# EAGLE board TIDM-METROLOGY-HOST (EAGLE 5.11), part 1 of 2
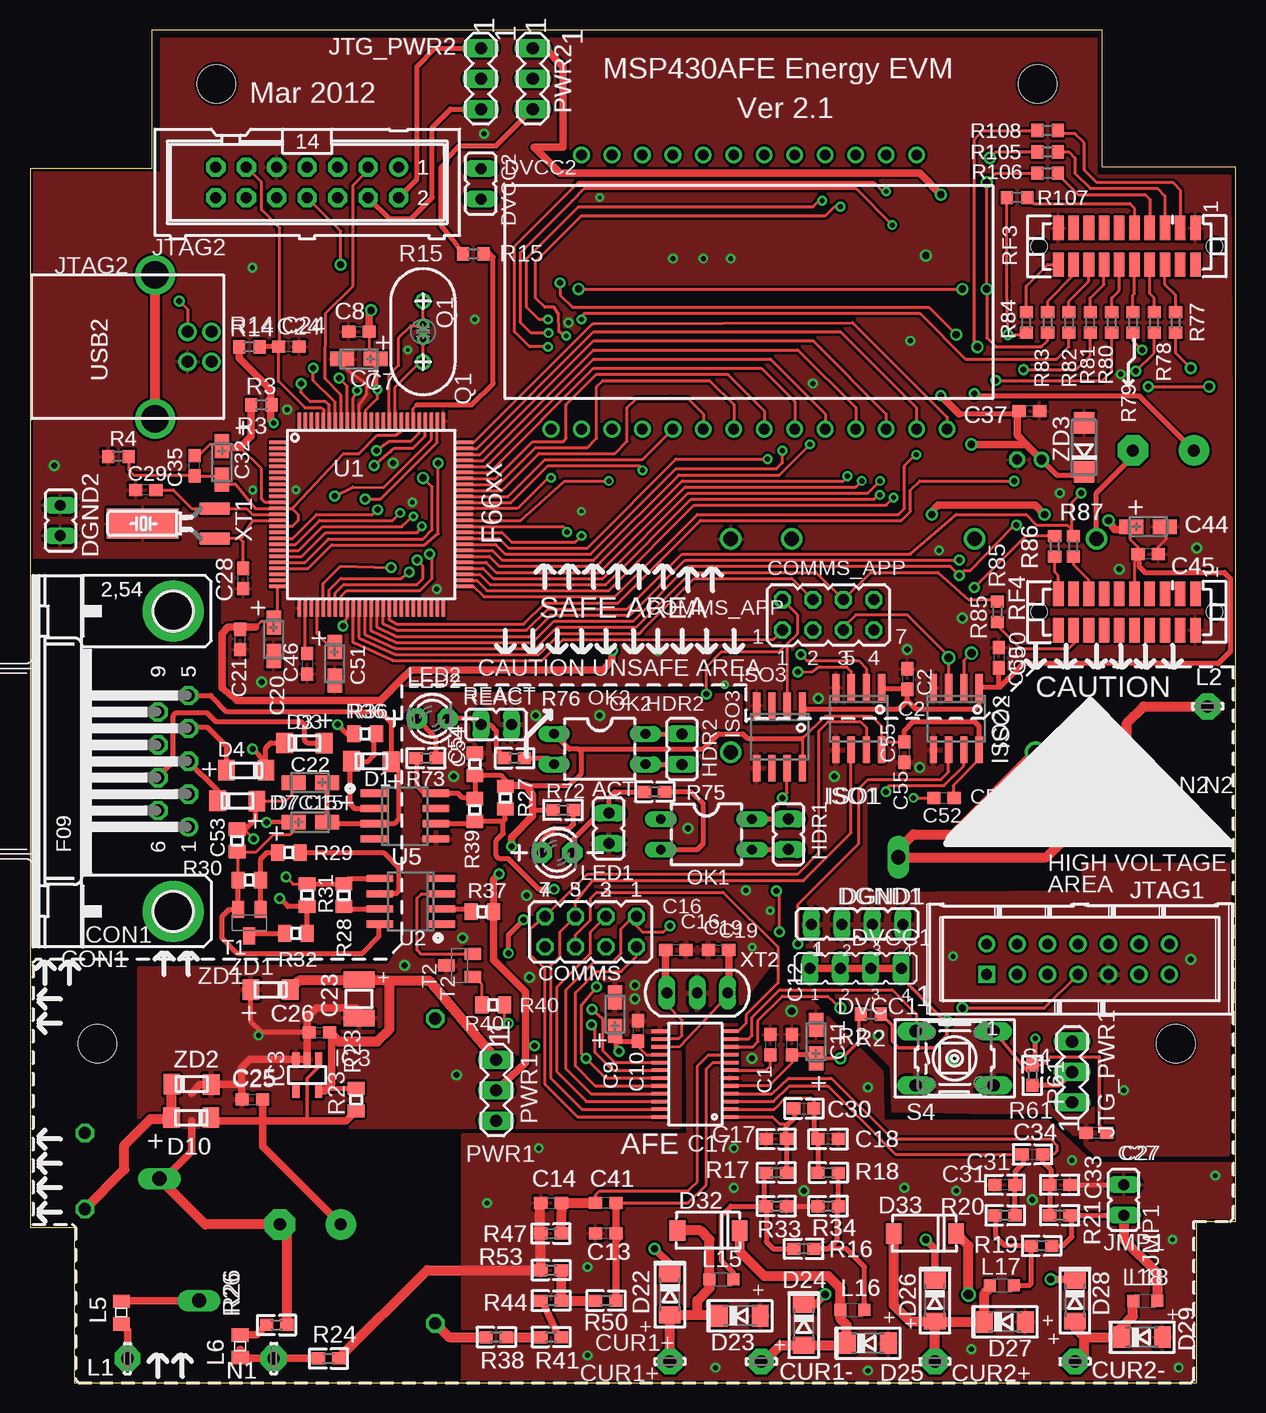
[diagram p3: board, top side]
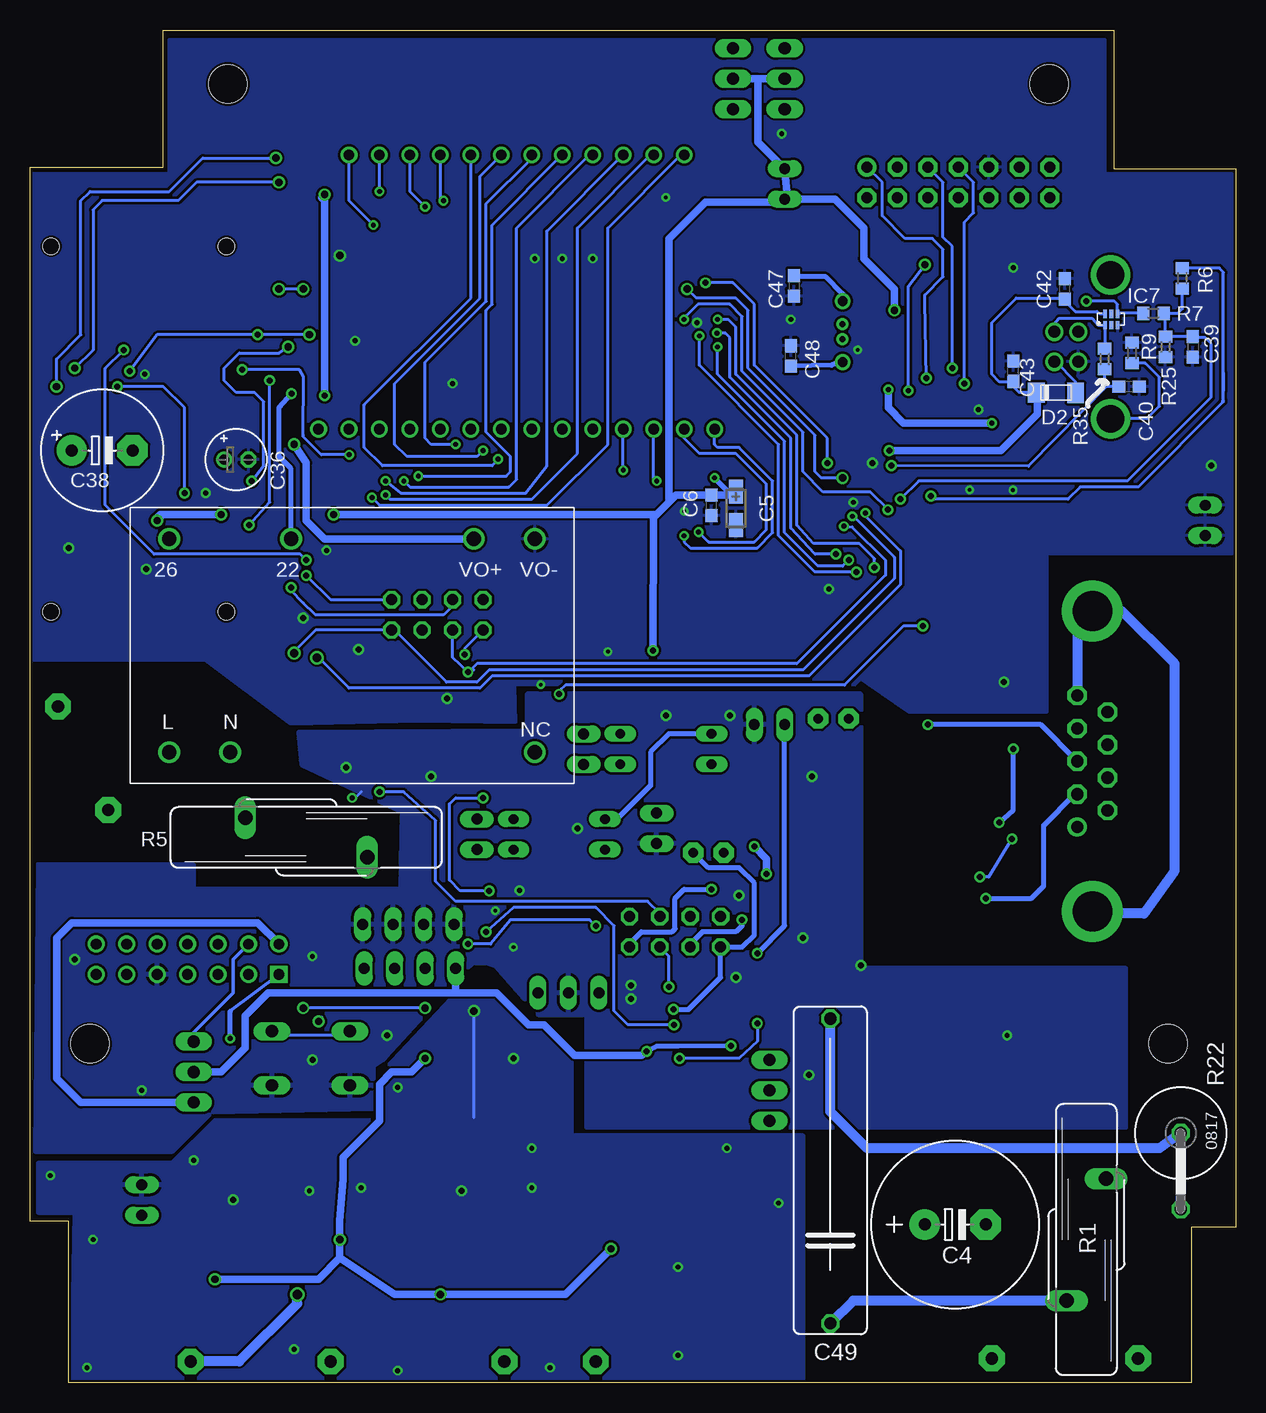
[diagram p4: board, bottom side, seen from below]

Size 100.51 x 112.78 mm. Coordinates in mm from the lower left corner, seen from the top.
Outline: 97.28,0 97.28,13.47 100.51,13.47 100.51,101.35 89.41,101.35 89.41,112.78 10.16,112.78 10.16,101.21 0,101.21 0,12.95 3.71,12.95 3.71,0 97.28,0
Copper layers (1*16): Top 0.035mm / dielectric 1.5mm / Bottom 0.035mm
Design rules "MSP430 PCBExpress ZA 06": minimum track width 8mil, minimum drill 14mil, track to track 8mil, track to pad 8mil, pad to pad 7mil, via to via 10mil, smd to smd 8mil, copper to edge 8mil, drill to drill 8mil, minimum pad ring 10mil, minimum via ring 8mil, stop-mask expansion 8mil, vias tented up to drill 15mil, thermal gap 10mil
Holes 3.2 mm at 84.01,108.27 5.62,28.27 95.52,28.27 15.53,108.27

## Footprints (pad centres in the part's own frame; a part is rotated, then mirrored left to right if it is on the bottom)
JP1 = drill 0.914 long: 1 0,-1.27; 2 0,1.27
C0603 = smd 1.1 x 1: 1 -0.85,0; 2 0.85,0
E5-13 = drill 1.016 pad 2.54 round: + -2.54,0 | drill 1.016 pad 2.54 octagon: - 2.54,0
CT3216 = smd 2 x 1.2: + -1.4,0; - 1.4,0
1210ELKO = smd 1.397 x 2.591: + 1.6,0; - -1.6,0
E2-5 = drill 0.813 pad 1.27 round: + -1.016,0 | drill 0.813 pad 1.27 octagon: - 1.016,0
E5-10,5 = drill 1.016 pad 2.54 round: + -2.54,0 | drill 1.016 pad 2.54 octagon: - 2.54,0
C225-062X268 = drill 1.016 octagon: 1 -14.097,0; 2 11.303,0
CSMD0805 = smd 1.092 x 1.397: 1 -0.94,0; 2 0.94,0
JP4Q = drill 0.914 octagon: 1 -3.81,-1.27; 2 -3.81,1.27; 3 -1.27,-1.27; 4 -1.27,1.27; 5 1.27,-1.27; 6 1.27,1.27; 7 3.81,-1.27; 8 3.81,1.27
F09HP = drill 1.016 pad 1.6 round: 1 -5.486,-1.27 | drill 1.016 pad 1.6 octagon: 2 -2.743,-1.27; 3 0,-1.27; 4 2.743,-1.27; 5 5.486,-1.27; 6 -4.115,1.27; 7 -1.372,1.27; 8 1.372,1.27; 9 4.115,1.27 | drill 3.302 pad 5.08 round: G1 -12.522,0; G2 12.522,0
LSP10 = drill 1.016 pad 2.159 octagon: MP 0,0
SOD-80 = smd 1.397 x 1.702: 1 1.397,-0.025; 2 -1.88,0
SOD80C = smd 1.4 x 1.8: A -1.7,0; C 1.7,0
DO-214 = smd 1.3 x 1.7: 1 0,0; 2 5.2,0
JP4 = drill 0.914 long: 1 -3.81,0; 2 -1.27,0; 3 1.27,0; 4 3.81,0
SOT23/5 = smd 0.6 x 1.2: 1 -0.95,-1.306; 2 0,-1.306; 3 0.95,-1.306; 4 0.95,1.306; 5 -0.95,1.306
DRY6 = smd 0.3 x 0.7: 1 -0.98,-2.254; 2 -0.457,-2.254; 3 0.066,-2.254; 4 0.066,-1.306; 5 -0.459,-1.306; 6 -0.98,-1.306
SO-08 = smd 0.6 x 2.2: 1 -1.905,-2.6; 2 -0.635,-2.6; 3 0.635,-2.6; 4 1.905,-2.6; 5 1.905,2.6; 6 0.635,2.6; 7 -0.635,2.6; 8 -1.905,2.6
MA07-2JTAG = drill 0.9 pad 1.422 square: 1 0,0 | drill 0.9 pad 1.422 round: 2 0,2.54; 3 2.54,0; 4 2.54,2.54; 5 5.08,0; 6 5.08,2.54; 7 7.62,0; 8 7.62,2.54; 9 10.16,0; 10 10.16,2.54; 11 12.7,0; 12 12.7,2.54; 13 15.24,0; 14 15.24,2.54
ML14 = drill 0.914 pad 1.6 round: 1 -7.62,-1.27 | drill 0.914 pad 1.6 octagon: 2 -7.62,1.27; 3 -5.08,-1.27; 4 -5.08,1.27; 5 -2.54,-1.27; 6 -2.54,1.27; 7 0,-1.27; 8 0,1.27; 9 2.54,-1.27; 10 2.54,1.27; 11 5.08,-1.27; 12 5.08,1.27; 13 7.62,-1.27; 14 7.62,1.27
MA03-1 = drill 1.016 long: 1 -2.54,0; 2 0,0; 3 2.54,0
0805@1 = smd 1.092 x 1.397: 1 -0.94,0; 2 0.94,0
L2012C = smd 1 x 1: 1 -1,0; 2 1,0
SBLCDA4 = drill 0.889 round: P$1 3.81,-20.32; P$2 6.35,-20.32; P$3 8.89,-20.32; P$4 11.43,-20.32; P$5 13.97,-20.32; P$6 16.51,-20.32; P$7 19.05,-20.32; P$8 21.59,-20.32; P$9 24.13,-20.32; P$10 26.67,-20.32; P$11 29.21,-20.32; P$12 31.75,-20.32; P$13 34.29,-20.32; P$14 36.83,-20.32; P$15 34.29,2.54; P$16 31.75,2.54; P$17 29.21,2.54; P$18 26.67,2.54; P$19 24.13,2.54; P$20 21.59,2.54; P$21 19.05,2.54; P$22 16.51,2.54; P$23 13.97,2.54; P$24 11.43,2.54; P$25 8.89,2.54; P$26 6.35,2.54
LED3MM = drill 0.8 pad 1.676 octagon: A -1.27,0; K 1.27,0
DIL04 = drill 0.813 long: 1 -3.81,1.27; 2 -3.81,-1.27; 3 3.81,-1.27; 4 3.81,1.27
HCTC = drill 0.5 round: 1 -0.635,0; 2 0.635,0 | drill 0.8 round: 3 -2.54,0; 4 2.54,0
S20K275 = drill 1.194 long: 1 -1.651,-5.08; 2 1.651,5.08
R0603 = smd 1 x 1.1: 1 -0.85,0; 2 0.85,0
R0603' = smd 1.1 x 1: 1 -0.85,0; 2 0.85,0
P0817V@1 = drill 1.016 octagon: 1 -5.08,0; 2 1.27,0
0805 = smd 1.092 x 1.397: 1 -0.94,0; 2 0.94,0
R0603@1 = smd 1 x 1.1: 1 -0.85,0; 2 0.85,0
TFM-110-02-SM-D-A-K = smd 2.032 x 0.889: 1 -1.524,5.715; 2 1.524,5.715; 3 -1.524,4.445; 4 1.524,4.445; 5 -1.524,3.175; 6 1.524,3.175; 7 -1.524,1.905; 8 1.524,1.905; 9 -1.524,0.635; 10 1.524,0.635; 11 -1.524,-0.635; 12 1.524,-0.635; 13 -1.524,-1.905; 14 1.524,-1.905; 15 -1.524,-3.175; 16 1.524,-3.175; 17 -1.524,-4.445; 18 1.524,-4.445; 19 -1.524,-5.715; 20 1.524,-5.715 | hole 1.359: 0,7.303; 0,-7.303
B3F-10XX = drill 1.016 long: 1 -3.251,2.261; 2 3.251,2.261; 3 -3.251,-2.261; 4 3.251,-2.261
SOT23-BEC = smd 1 x 1.4: B -0.95,-1.1; C 0,1.1; E 0.95,-1.1
PZ100 = smd 1.4 x 0.3: 1 -7.8,6; 2 -7.8,5.5; 3 -7.8,5; 4 -7.8,4.5; 5 -7.8,4; 6 -7.8,3.5; 7 -7.8,3; 8 -7.8,2.5; 9 -7.8,2; 10 -7.8,1.5; 11 -7.8,1; 12 -7.8,0.5; 13 -7.8,0; 14 -7.8,-0.5; 15 -7.8,-1; 16 -7.8,-1.5; 17 -7.8,-2; 18 -7.8,-2.5; 19 -7.8,-3; 20 -7.8,-3.5; 21 -7.8,-4; 22 -7.8,-4.5; 23 -7.8,-5; 24 -7.8,-5.5; 25 -7.8,-6; 51 7.8,-6; 52 7.8,-5.5; 53 7.8,-5; 54 7.8,-4.5; 55 7.8,-4; 56 7.8,-3.5; 57 7.8,-3; 58 7.8,-2.5; 59 7.8,-2; 60 7.8,-1.5; 61 7.8,-1; 62 7.8,-0.5; 63 7.8,0; 64 7.8,0.5; 65 7.8,1; 66 7.8,1.5; 67 7.8,2; 68 7.8,2.5; 69 7.8,3; 70 7.8,3.5; 71 7.8,4; 72 7.8,4.5; 73 7.8,5; 74 7.8,5.5; 75 7.8,6 | smd 0.3 x 1.4: 26 -6,-7.8; 27 -5.5,-7.8; 28 -5,-7.8; 29 -4.5,-7.8; 30 -4,-7.8; 31 -3.5,-7.8; 32 -3,-7.8; 33 -2.5,-7.8; 34 -2,-7.8; 35 -1.5,-7.8; 36 -1,-7.8; 37 -0.5,-7.8; 38 0,-7.8; 39 0.5,-7.8; 40 1,-7.8; 41 1.5,-7.8; 42 2,-7.8; 43 2.5,-7.8; 44 3,-7.8; 45 3.5,-7.8; 46 4,-7.8; 47 4.5,-7.8; 48 5,-7.8; 49 5.5,-7.8; 50 6,-7.8; 76 6,7.8; 77 5.5,7.8; 78 5,7.8; 79 4.5,7.8; 80 4,7.8; 81 3.5,7.8; 82 3,7.8; 83 2.5,7.8; 84 2,7.8; 85 1.5,7.8; 86 1,7.8; 87 0.5,7.8; 88 0,7.8; 89 -0.5,7.8; 90 -1,7.8; 91 -1.5,7.8; 92 -2,7.8; 93 -2.5,7.8; 94 -3,7.8; 95 -3.5,7.8; 96 -4,7.8; 97 -4.5,7.8; 98 -5,7.8; 99 -5.5,7.8; 100 -6,7.8
SO08 = smd 0.6 x 2.2: 1 -1.905,-2.6; 2 -0.635,-2.6; 3 0.635,-2.6; 4 1.905,-2.6; 5 1.905,2.6; 6 0.635,2.6; 7 -0.635,2.6; 8 -1.905,2.6
MSP430AFE_24TSSOP = smd 1.4 x 0.3: P$1 -3,3.75; P$2 -3,3.1; P$3 -3,2.45; P$4 -3,1.8; P$5 -3,1.15; P$6 -3,0.5; P$7 -3,-0.15; P$8 -3,-0.8; P$9 -3,-1.45; P$10 -3,-2.1; P$11 -3,-2.75; P$12 -3,-3.4; P$13 2.85,-3.4; P$14 2.85,-2.75; P$15 2.85,-2.1; P$16 2.85,-1.45; P$17 2.85,-0.8; P$18 2.85,-0.15; P$19 2.85,0.5; P$20 2.85,1.15; P$21 2.85,1.8; P$22 2.85,2.45; P$23 2.85,3.1; P$24 2.85,3.75
CUI_XR = drill 1.2 round: 22 10.16,0; 26 0,0; L 0,-17.78; N 5.08,-17.78; NC 30.48,-17.78; VO+ 25.4,0; VO- 30.48,0
USB_BUCHSE = drill 1 round: 1 1.25,7; 2 -1.25,7; 3 -1.25,5; 4 1.25,5 | drill 2.3 round: 5 -6,2.3; 6 6,2.3
CM200T = smd 1 x 2.5: P1 -1.25,-5; P2 1.25,-5 | smd 2.5 x 6: P3 0,1
X905 = drill 0.914 long: 1 -2.54,0; 2 0,0; 3 2.54,0
DO214AC = smd 1.8 x 1.7: A 2.05,0; C -2.05,0

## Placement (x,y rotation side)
ACT  [JP1]  48.26,46.23 180 top
C1  0.1u  [C0603]  61.72,28.2 270 top
C2  0.1u  [C0603]  73.15,58.68 270 top
C4  2200uF  [E5-13]  23.37,13.21 0 bottom
C5  10u  [CT3216]  41.66,72.9 270 bottom
C6  0.1u  [C0603]  43.69,73.16 90 bottom
C7  10u  [CT3216]  27.43,85.35 180 top
C8  0.1u  [C0603]  27.43,87.64 0 top
C9  10u  [CT3216]  48.77,30.74 90 top
C10  0.1u  [C0603]  50.67,29.34 270 top
C11  10u  [CT3216]  65.53,28.45 90 top
C12  0.1u  [C0603]  63.5,28.2 270 top
C13  47pF  [C0603]  48.01,12.45 180 top
C14  47pF  [C0603]  43.43,14.99 0 top
C15  10u  [CT3216]  23.37,46.74 0 top
C16  12pF  [C0603]  53.85,36.07 180 top
C17  47pF  [C0603]  62.23,20.33 180 top
C18  47pF  [C0603]  66.55,20.33 180 top
C19  12pF  [C0603]  57.4,36.07 0 top
C20  10u  [CT3216]  20.32,61.98 270 top
C21  0.1u  [C0603]  17.53,61.98 90 top
C22  10u  [CT3216]  23.37,50.04 180 top
C23  10u  [1210ELKO]  27.43,32.01 90 top
C24  2.2n  [C0603]  21.59,86.37 180 top
C25  0.1u  [C0603]  18.54,23.63 0 top
C26  0.1u  [C0603]  24.13,29.22 0 top
C27  2.2n  [C0603]  88.9,20.83 180 top
C28  12pF  [C0603]  17.78,67.06 90 top
C29  12pF  [C0603]  9.65,74.43 180 top
C30  15nF  [C0603]  64.52,22.87 0 top
C31  47pF  [C0603]  81.28,16.52 180 top
C32  10u  [CT3216]  16,76.71 270 top
C33  47pF  [C0603]  85.85,16.52 180 top
C34  15nF  [C0603]  83.57,19.06 0 top
C35  0.1u  [C0603]  13.72,76.46 90 top
C36  150uF  [E2-5]  83.31,76.97 0 bottom
C37  0.1u  [C0603]  83.31,81.03 0 top
C38  4.7u/400V  [E5-10,5]  94.49,77.73 0 bottom
C39  10p  [C0603]  3.56,86.37 270 bottom
C40  10p  [C0603]  8.89,83.06 0 bottom
C41  15nF  [C0603]  48.01,14.99 180 top
C42  4.7u  [C0603]  14.22,91.19 90 bottom
C43  0.1u  [C0603]  18.54,84.33 90 bottom
C44  10u  [CT3216]  93.22,71.38 0 top
C45  0.1u  [C0603]  93.22,69.09 180 top
C46  470n  [C0603]  23.11,59.95 270 top
C47  47pF  [C0603]  36.83,91.45 270 bottom
C48  47pF  [C0603]  37.08,85.6 90 bottom
C49  910n / 400V  [C225-062X268]  33.78,19.06 90 bottom
C50  0.1u  [C0603]  80.77,60.46 270 top
C51  10u  [CT3216]  25.4,59.95 270 top
C52  0.1u  [C0603]  76.2,48.77 0 top
C53  0.1u  [CSMD0805]  17.27,45.22 90 top
C54  0.1u  [CSMD0805]  37.08,51.57 270 top
C55  0.1u  [C0603]  72.9,52.58 90 top
COMMS  [JP4Q]  46.74,37.6 180 top
COMMS_APP  [JP4Q]  66.55,64.01 0 top
CON1  F09HP  [F09HP]  11.94,51.82 90 top
CUR1+  LSP10  [LSP10]  53.34,1.78 0 top
CUR1-  LSP10  [LSP10]  60.96,1.78 0 top
CUR2+  LSP10  [LSP10]  75.44,1.78 0 top
CUR2-  LSP10  [LSP10]  87.12,1.78 0 top
D1  LL103A  [SOD-80]  28.7,51.82 0 top
D2  LL103A  [SOD-80]  14.73,82.56 0 bottom
D3  LL103A  [SOD-80]  23.11,53.35 0 top
D4  LL103A  [SOD-80]  17.78,51.06 180 top
D7  LL103A  [SOD-80]  17.53,48.52 0 top
D10  LL103A  [SOD-80]  13.21,22.1 180 top
D22  1N4148  [SOD80C]  53.34,7.37 90 top
D23  1N4148  [SOD80C]  59.18,5.59 180 top
D24  1N4148  [SOD80C]  64.52,4.83 90 top
D25  1N4148  [SOD80C]  69.85,3.31 180 top
D26  1N4148  [SOD80C]  75.44,6.86 90 top
D27  1N4148  [SOD80C]  81.28,5.09 180 top
D28  1N4148  [SOD80C]  87.12,6.86 90 top
D29  1N4148  [SOD80C]  92.71,3.82 180 top
D32  SMAJ5.0CA  [DO-214]  59.18,12.71 180 top
D33  SMAJ5.0CA  [DO-214]  77.22,12.45 180 top
DGND1  [JP4]  68.96,38.23 0 top
DGND2  [JP1]  2.54,71.89 0 top
DVCC1  [JP4]  68.83,34.55 0 top
DVCC2  [JP1]  37.59,99.95 180 top
HDR1  [JP1]  63.25,45.73 180 top
HDR2  [JP1]  54.36,52.84 180 top
IC3  TPS77033  [SOT23/5]  23.11,25.66 180 top
IC7  TPD4E004  [DRY6]  9.91,90.43 0 bottom
ISO1  ISO7420FE  [SO-08]  69.09,55.38 180 top
ISO2  ISO7421FE  [SO-08]  77.22,55.38 180 top
ISO3  ISO7421FE  [SO-08]  62.48,53.85 180 top
JMP1  [JP1]  91.19,15.25 180 top
JTAG1  [MA07-2JTAG]  79.76,34.04 0 top
JTAG2  ML14  [ML14]  23.11,100.08 180 top
JTG_PWR1  [MA03-1]  86.87,25.91 90 top
JTG_PWR2  [MA03-1]  37.59,108.72 270 top
L1  LSP10  [LSP10]  8.13,2.04 90 top
L2  LSP10  [LSP10]  98.17,56.39 0 top
L5  1uH  [0805@1]  7.62,5.85 90 top
L6  1uH  [0805@1]  17.53,3.05 90 top
L15  BLM21BD121SN1D  [L2012C]  57.66,8.64 0 top
L16  BLM21BD121SN1D  [L2012C]  68.58,6.1 0 top
L17  BLM21BD121SN1D  [L2012C]  81.03,8.13 0 top
L18  BLM21BD121SN1D  [L2012C]  92.96,6.86 0 top
LCD1  SBLCDA4  [SBLCDA4]  39.62,99.83 0 top
LED1  [LED3MM]  43.94,44.2 0 top
LED2  [LED3MM]  33.53,55.38 0 top
N1  LSP10  [LSP10]  20.32,2.04 90 top
N2  LSP10  [LSP10]  93.98,47.76 0 top
OK1  TIL191  [DIL04]  56.39,45.73 0 top
OK2  TIL191  [DIL04]  47.5,52.84 0 top
PWR1  [MA03-1]  38.86,24.39 270 top
PWR2  [MA03-1]  41.91,108.72 270 top
Q1  HCTC_XTL_4  [HCTC]  32.77,87.64 270 top
R1  S20K275  [S20K275]  12.45,11.94 180 bottom
R2  10  [R0603]  70.1,30.74 180 top
R3  10  [R0603]  19.3,81.54 180 top
R4  0  [R0603]  7.37,77.22 0 top
R5  S20K275  [S20K275]  77.47,45.47 90 bottom
R6  1.4k  [R0603]  4.45,92.08 270 bottom
R7  27  [R0603]  6.86,89.16 180 bottom
R9  33k  [R0603]  8.64,85.86 270 bottom
R14  47k  [R0603]  18.29,86.37 0 top
R15  0  [R0603]  36.96,94.11 0 top
R16  6.8  [R0603']  64.52,11.18 180 top
R17  1K  [R0603']  62.23,17.53 180 top
R18  1K  [R0603']  66.55,17.53 0 top
R19  6.8  [R0603']  84.33,11.44 0 top
R20  1K  [R0603']  81.28,13.98 0 top
R21  1K  [R0603']  85.85,13.98 180 top
R22  560R / 5W  [P0817V@1]  4.57,15.75 270 bottom
R23  DNP  [0805]  27.18,23.63 90 top
R24  0  [R0603']  24.89,2.04 180 top
R25  1M  [R0603]  5.84,86.37 90 bottom
R26  0  [R0603']  20.57,4.83 180 top
R27  -  [0805]  39.62,48.77 90 top
R28  DNP  [0805]  26.16,40.65 90 top
R29  1k  [0805]  21.59,44.2 180 top
R30  10k  [0805]  18.29,41.92 180 top
R31  1.5k  [0805]  23.11,40.65 270 top
R32  220  [0805]  22.17,37.47 180 top
R33  DNP  [R0603']  62.23,14.74 180 top
R34  0  [R0603']  66.55,14.74 180 top
R35  27  [R0603]  10.92,85.35 90 bottom
R36  1k  [0805]  27.94,54.11 180 top
R37  68  [0805]  37.71,39.27 180 top
R38  330k  [R0603']  38.86,3.82 0 top
R39  2.2k  [0805]  37.08,47.76 270 top
R40  2.2k  [0805]  38.61,31.5 180 top
R41  330k  [R0603']  43.43,3.82 0 top
R44  330k  [R0603']  43.43,6.86 0 top
R47  1K  [R0603']  43.43,12.45 180 top
R50  100  [R0603']  48.01,6.86 0 top
R53  1.5K  [R0603']  43.43,9.4 0 top
R61  47k  [R0603']  83.57,25.66 90 top
R72  1K  [R0603']  44.45,47.76 180 top
R73  1K  [R0603']  33.02,52.08 180 top
R75  1K  [R0603']  52.07,49.28 0 top
R76  1K  [R0603']  40.39,52.08 0 top
R77  0  [R0603@1]  95.5,88.4 270 top
R78  0  [R0603@1]  93.73,88.4 270 top
R79  0  [R0603@1]  91.95,88.4 270 top
R80  0  [R0603@1]  90.17,88.4 270 top
R81  0  [R0603@1]  88.39,88.4 270 top
R82  0  [R0603@1]  86.61,88.4 270 top
R83  0  [R0603@1]  84.84,88.4 270 top
R84  0  [R0603@1]  83.06,88.4 270 top
R85  0  [R0603@1]  80.64,64.29 270 top
R86  0  [R0603@1]  85.42,69.75 90 top
R87  0  [R0603@1]  86.97,69.75 90 top
R105  0  [R0603@1]  84.84,102.62 0 top
R106  0  [R0603@1]  84.84,100.84 0 top
R107  0  [R0603@1]  82.3,98.81 0 top
R108  0  [R0603@1]  84.84,104.4 0 top
REACT  [JP1]  38.86,54.87 270 top
RF3  [TFM-110-02-SM-D-A-K]  91.44,94.75 270 top
RF4  [TFM-110-02-SM-D-A-K]  91.44,64.27 270 top
S4  [B3F-10XX]  77.09,27.06 0 top
T1  BC860B/BC857B  [SOT23-BEC]  18.29,38.36 180 top
T2  BC860B/BC857B  [SOT23-BEC]  35.81,34.8 90 top
U1  F66XX---PZ100  [PZ100]  28.45,72.4 0 top
U2  PS8802  [SO08]  31.75,40.14 90 top
U5  PS8802  [SO08]  31.24,47.25 270 top
U$1  MSP430AFE_24TSSOP  [MSP430AFE_24TSSOP]  55.37,25.91 180 top
U$2  CUI_XR  [CUI_XR]  88.9,70.36 0 bottom
USB2  [USB_BUCHSE]  8.13,86.37 270 top
XT1  XT1  [CM200T]  10.41,71.63 90 top
XT2  XT2  [X905]  55.63,32.52 0 top
ZD1  DNP (3.3V)  [SOD-80]  19.81,32.77 180 top
ZD2  5.1V  [SOD-80]  13.72,24.9 0 top
ZD3  SMAJ5.0ABCT  [DO214AC]  87.88,77.98 90 top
